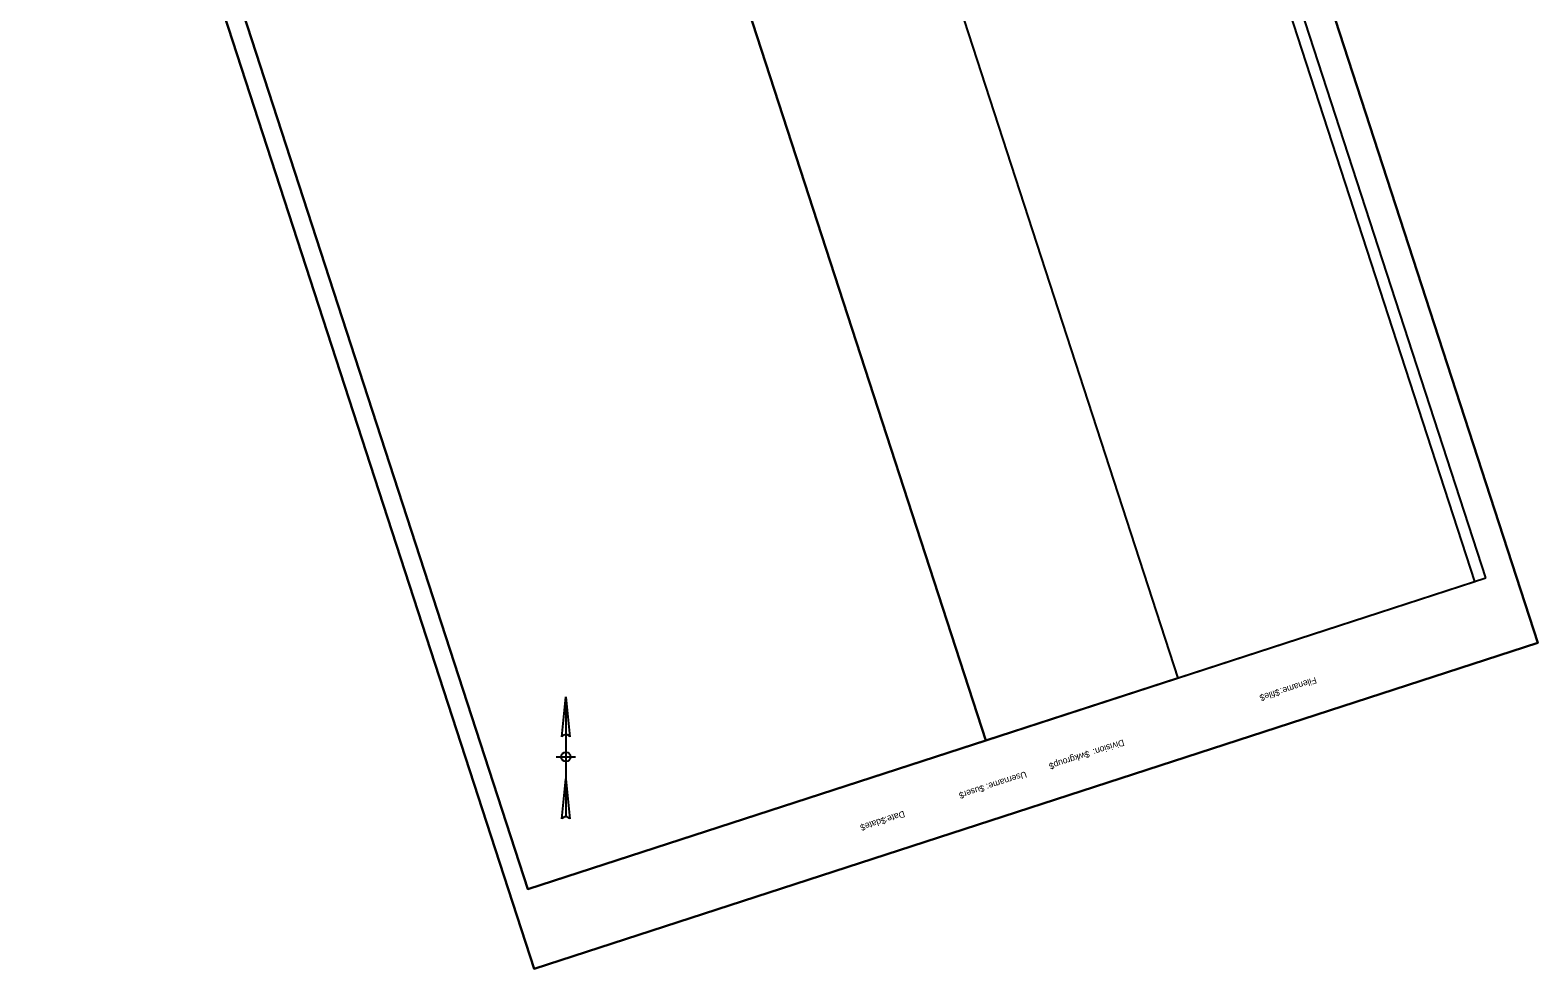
# Model space of a CAD drawing. Extents: x 1038278 to 1039064, y 778332 to 779310.
# Drawn here: x 1038278 to 1039064, y 778332 to 778821 of the extents above; entities that cross this region are included whole.
import ezdxf

# ---------------------------------------------------------------- set-up
doc = ezdxf.new("R2010")
doc.units = 0
for name, color, linetype in [('CLIPS', 7, 'Continuous'), ('Default', 7, 'Continuous'), ('PLOT BOUNDARY', 7, 'Continuous')]:
    doc.layers.add(name, color=color, linetype=linetype)

msp = doc.modelspace()

# ---------------------------------------------------------------- linework, layer by layer
at = {"layer": 'CLIPS'}
for points in [[(1039031.23, 778533.84), (1038799.47, 779247.13), (1038544.58, 779164.32), (1038776.35, 778451.02)], [(1038537.72, 778373.49), (1038305.95, 779086.78), (1038644.74, 779196.86), (1038876.5, 778483.57)], [(1038776.35, 778451.02), (1038544.58, 779164.32), (1038305.94, 779086.78), (1038537.7, 778373.48)]]:
    msp.add_lwpolyline(points, close=True, dxfattribs=at)
at = {"layer": 'Default'}
for p, q in [((1039037.02, 778535.72), (1038789.81, 779296.57)), ((1038290.5, 779134.33), (1038537.72, 778373.49)), ((1038537.72, 778373.49), (1039037.02, 778535.72)), ((1038555.44, 778452.9), (1038557.52, 778473.74)), ((1038557.52, 778473.74), (1038557.52, 778411.24)), ((1038557.52, 778473.74), (1038559.61, 778452.9)), ((1038552.52, 778442.49), (1038562.52, 778442.49)), ((1038555.44, 778410.12), (1038557.52, 778430.95)), ((1038557.52, 778430.95), (1038559.61, 778410.12))]:
    msp.add_line(p, q, dxfattribs=at)
msp.add_lwpolyline([(1039064.07, 778501.96), (1038801.41, 779310.36), (1038278.33, 779140.4), (1038540.99, 778332)], close=True, dxfattribs=at)
msp.add_circle((1038557.52, 778442.49), 2.5, dxfattribs=at)
for centre in [(1038557.52, 778451.52), (1038557.52, 778408.74)]:
    msp.add_arc(centre, 2.5, 33.55731, 146.44269, dxfattribs=at)
at = {"layer": 'PLOT BOUNDARY'}
msp.add_lwpolyline([(1038540.99, 778332), (1038278.33, 779140.4), (1038801.41, 779310.36), (1039064.07, 778501.96)], close=True, dxfattribs=at)

# ---------------------------------------------------------------- texts
at = {"layer": 'Default'}
for s, p in [('Filename:', (1038948.12, 778484.15)), ('$file$', (1038928.97, 778477.93)), ('$wkgroup$', (1038829.85, 778445.72)), ('Division:', (1038847.93, 778451.6)), ('Username:', (1038797.04, 778435.06)), ('$user$', (1038775.06, 778427.92)), ('Date:', (1038733.56, 778414.44)), ('$date$', (1038723.63, 778411.21))]:
    msp.add_text(s, height=3.348, rotation=198, dxfattribs=at).set_placement(p)

doc.saveas('drawing.dxf')
